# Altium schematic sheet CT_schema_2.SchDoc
size 321 x 189 mm
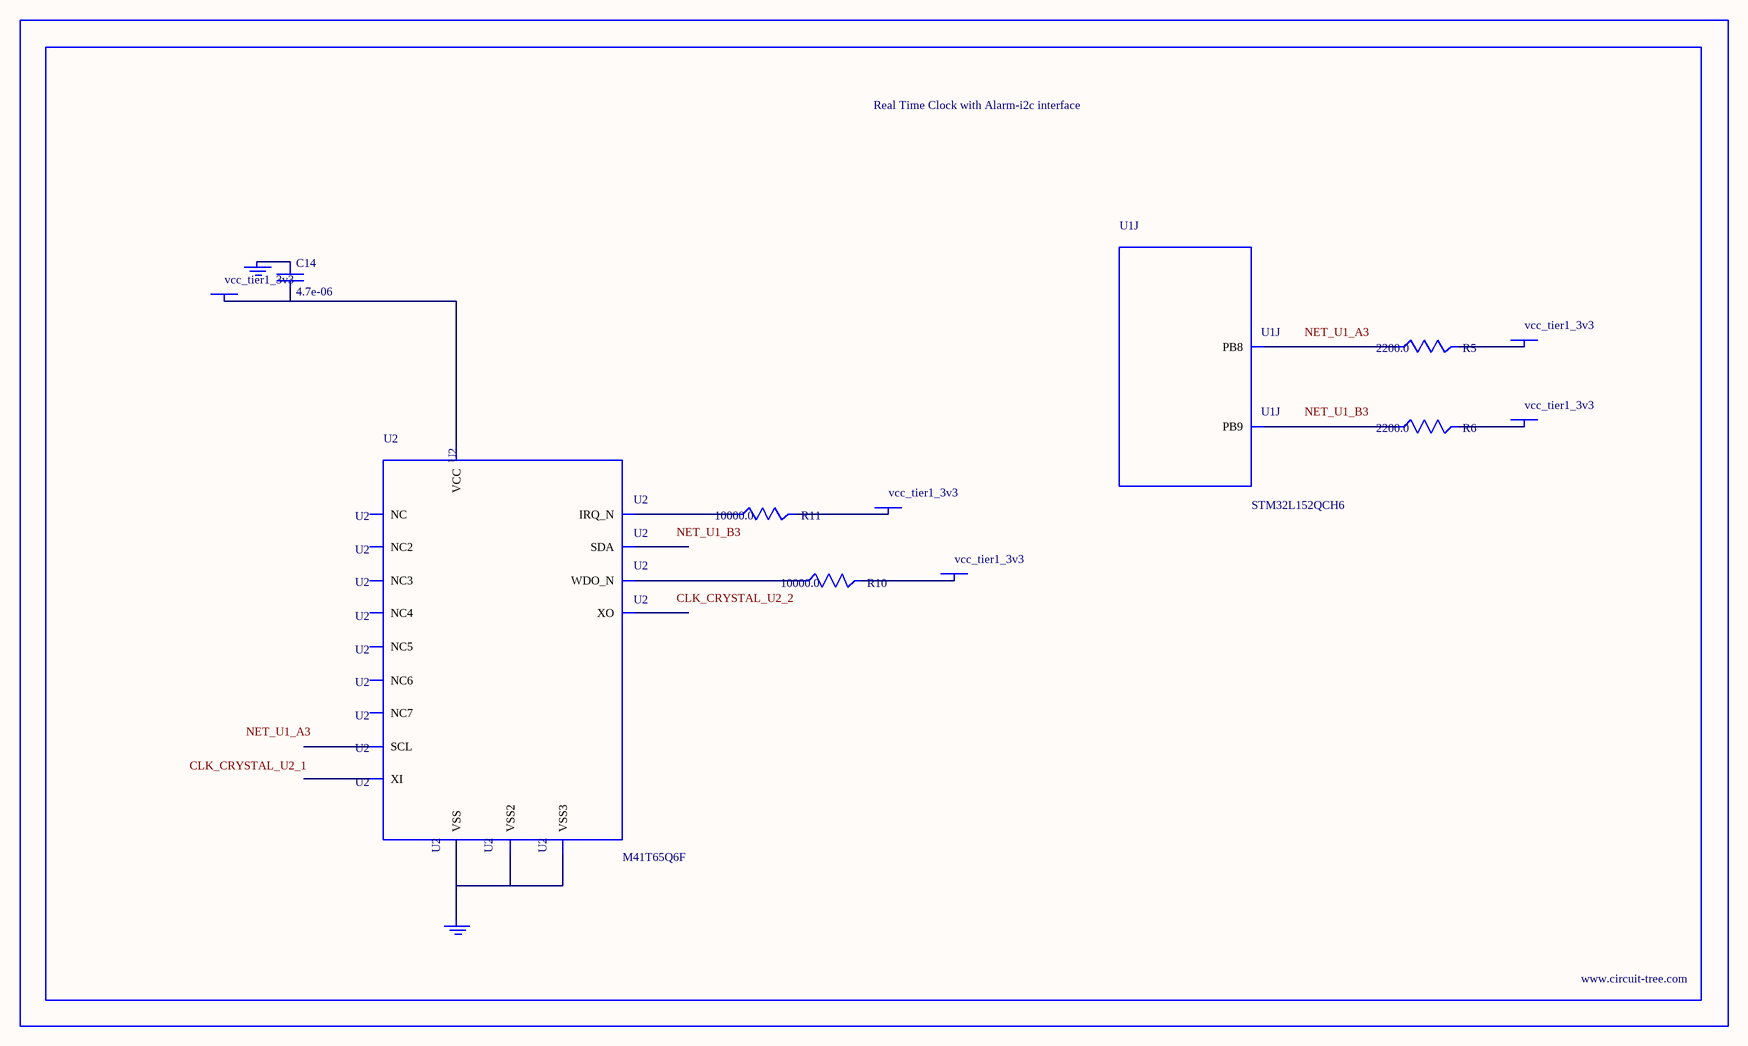
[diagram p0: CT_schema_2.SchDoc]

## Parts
BORDER1  (no value)
C14  4.7e-06  [C0805]
GND_INSTANCE_1_0  (no value)
GND_INSTANCE_1_1  (no value)
POWER_INSTANCE_1_0  vcc_tier1_3v3
POWER_INSTANCE_1_1  vcc_tier1_3v3
POWER_INSTANCE_1_2  vcc_tier1_3v3
POWER_INSTANCE_1_3  vcc_tier1_3v3
POWER_INSTANCE_1_4  vcc_tier1_3v3
R5  2200.0  [R0603]
R6  2200.0  [R0603]
R10  10000.0  [R0603]
R11  10000.0  [R0603]
U1  STM32L152QCH6  [UFBGA132]  (part J of 12)
U2  M41T65Q6F  [M41T65_QFN-16]

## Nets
NetC14_1: C14.1 GND_INSTANCE_1_0.0(GND)
NetC14_2: C14.2 POWER_INSTANCE_1_2.0(PWR) U2.14(VCC)
NetGND_INSTANCE_1_1_0: GND_INSTANCE_1_1.0(GND) U2.3(VSS) U2.5(VSS2) U2.17(VSS3)
NetPOWER_INSTANCE_1_0_0: POWER_INSTANCE_1_0.0(PWR) R10.2
NetPOWER_INSTANCE_1_1_0: POWER_INSTANCE_1_1.0(PWR) R11.2
NetPOWER_INSTANCE_1_3_0: POWER_INSTANCE_1_3.0(PWR) R5.2
NetPOWER_INSTANCE_1_4_0: POWER_INSTANCE_1_4.0(PWR) R6.2
NetR5_1: R5.1 U1.A3(PB8)
NetR6_1: R6.1 U1.B3(PB9)
NetR10_1: R10.1 U2.4(WDO_N)
NetR11_1: R11.1 U2.11(IRQ_N)

Not connected (* = marked no-connect by the designer): U2 1(XI) 2(XO) 6(NC) 7(NC2) 8(NC3) 9(SDA) 10(SCL) 12(NC4) 13(NC5) 15(NC6) 16(NC7)

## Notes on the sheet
- Labels drawn without touching a wire or pin: CLK_CRYSTAL_U2_1, CLK_CRYSTAL_U2_2, NET_U1_A3, NET_U1_B3

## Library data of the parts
BORDER1 = BORDER_PAGE1
C14 = C0805C475K4RACTU
GND_INSTANCE_1_0 GND_INSTANCE_1_1 = GND
POWER_INSTANCE_1_0-POWER_INSTANCE_1_4 = PWR
R5 R6 = RC0603JR-072K2L
R10 R11 = RC0603JR-0710KL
